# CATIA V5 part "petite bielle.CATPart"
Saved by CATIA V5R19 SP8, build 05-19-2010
Part number: petite bielle
Bounding box of the stored display mesh (mm): x -16 to 2, y -2.965 to 2.965, z -16.824 to 2.824
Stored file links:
  C:\Users\rcousturie\Desktop\EU_thinkMotion\iao\IAO_MMS_Groupe1\glenerrant\glenerrant\Nouveau dossier\petite bielle.CATPart
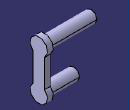
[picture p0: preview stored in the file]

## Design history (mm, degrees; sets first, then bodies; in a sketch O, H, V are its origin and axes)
Parameters
  `Largeur bielle` = 2 mm
Set1
  Point1: (0, 0, 0)
  Point2: (0, 0, -14)
Body1 (main body)
  Line1: stored without definition
  Line2: stored without definition
  Sketch1 on yz-plane, origin (0, 0, 0), H (0, 1, 0), V (0, 0, 1)
    arc A1 centre (0, 0) radius 3 from (2, -2.2361) to (-2, -2.2361) ccw
    point P1 (0, 0)
    arc A2 centre (0, -14) radius 3 from (-2, -11.7639) to (2, -11.7639) ccw
    point P2 (0, -14)
    reference projected point E1 (0, 0) from Point1
    reference projected point E2 (0, -14) from Point2
    line L1 (-2, -11.7639) -> (-2, -2.2361)
    line L2 (2, -2.2361) -> (2, -11.7639)
    reference projected line E3 (0, 0) -> (0, -14) from Line1
    reference projected line E4 (0, 0) -> (0, -14) from Line1
    reference projected line E5 (0, 0) -> (0, -14) from Line2
    radius A1 = 3
    radius A2 = 3
    distance E5 L1 = 2 {= `Largeur bielle`}
    coincidence: P1 E1, P2 E2
    symmetry: L2 L1 E3
    parallelism: L2 L1, L1 E4
  Pad1: profile Sketch1, direction (1, 0, 0), length 2
  Sketch2 on start face of Pad1, origin (0, 0, 0), H (0, -1, 0), V (0, 0, 1)
    circle A1 centre (0, 0) radius 2
    point P1 (0, 0)
    reference projected point E1 (0, 0) from Point1
    radius A1 = 2
    coincidence: P1 E1
  Pad2: profile Sketch2, direction (-1, 0, 0), length 16
  Sketch3 on start face of Pad1, origin (0, 0, 0), H (0, -1, 0), V (0, 0, 1)
    circle A1 centre (0, -14) radius 2
    point P1 (0, -14)
    reference projected point E1 (0, -14) from Point2
    radius A1 = 2
    coincidence: P1 E1
  Pad3: profile Sketch3, direction (-1, 0, 0), length 10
